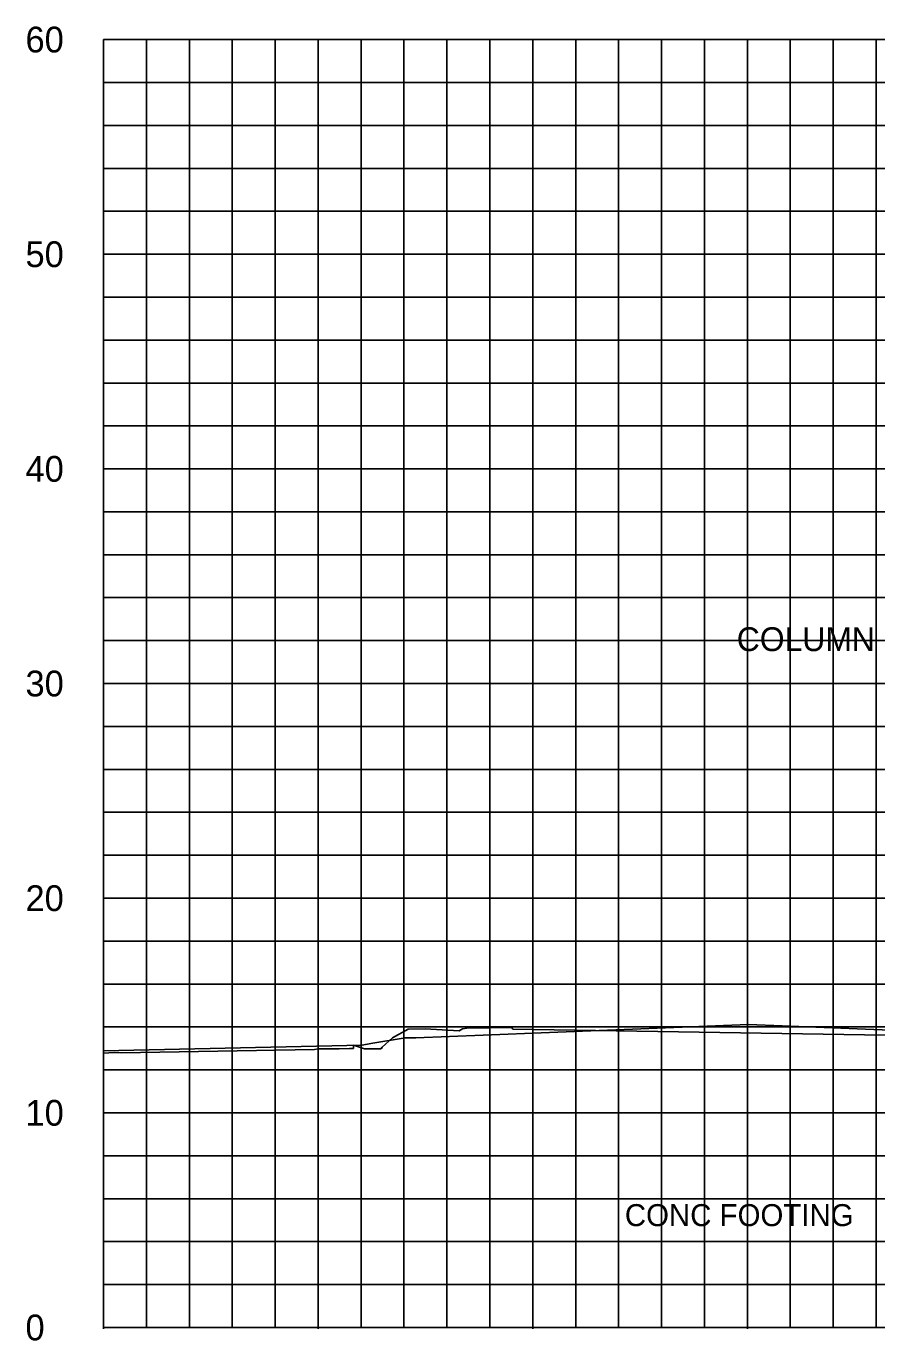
# Model space of a CAD drawing. Extents: x 2193008 to 2198143, y 1236112 to 1237864.
# Drawn here: x 2194694.1 to 2194733.7, y 1237162.5 to 1237223.7 of the extents above; entities that cross this region are included whole.
import ezdxf

# ---------------------------------------------------------------- set-up
doc = ezdxf.new("R2010")
doc.units = 0
for name, color, linetype in [('31', 7, 'Continuous'), ('60', 7, 'Continuous'), ('CL-CNST', 7, 'Continuous'), ('Level 55', 7, 'Continuous'), ('Level 62', 7, 'Continuous'), ('M-ROADS', 7, 'Continuous')]:
    doc.layers.add(name, color=color, linetype=linetype)

msp = doc.modelspace()

# ---------------------------------------------------------------- linework, layer by layer
at = {"layer": '60'}
for p, q in [((2194697.688, 1237163.106), (2194697.688, 1237223.106)), ((2194697.688, 1237163.046), (2194697.688, 1237163.106)), ((2194697.688, 1237163.106), (2194827.688, 1237163.106)), ((2194707.688, 1237163.046), (2194707.688, 1237163.106)), ((2194717.688, 1237163.046), (2194717.688, 1237163.106)), ((2194727.688, 1237163.046), (2194727.688, 1237163.106))]:
    msp.add_line(p, q, dxfattribs=at)
at = {"layer": 'CL-CNST'}
msp.add_lwpolyline([(2194697.688, 1237175.995), (2194709.741, 1237176.26), (2194710.142, 1237176.328), (2194711.741, 1237176.6), (2194711.841, 1237176.6), (2194712.241, 1237176.6), (2194715.381, 1237176.726), (2194727.74, 1237177.22), (2194730.881, 1237177.095), (2194743.239, 1237176.6), (2194743.639, 1237176.6), (2194743.739, 1237176.6), (2194744.14, 1237176.532), (2194745.739, 1237176.26), (2194755.304, 1237176.05), (2194793.33, 1237175.213)], dxfattribs=at)
at = {"layer": 'Level 62'}
for p, q in [((2194697.688, 1237223.106), (2194827.688, 1237223.106)), ((2194699.688, 1237163.106), (2194699.688, 1237223.106)), ((2194701.688, 1237163.106), (2194701.688, 1237223.106)), ((2194703.688, 1237163.106), (2194703.688, 1237223.106)), ((2194705.688, 1237163.106), (2194705.688, 1237223.106)), ((2194707.688, 1237163.106), (2194707.688, 1237223.106)), ((2194709.688, 1237163.106), (2194709.688, 1237223.106)), ((2194711.688, 1237163.106), (2194711.688, 1237223.106)), ((2194713.688, 1237163.106), (2194713.688, 1237223.106)), ((2194715.688, 1237163.106), (2194715.688, 1237223.106)), ((2194717.688, 1237163.106), (2194717.688, 1237223.106)), ((2194719.688, 1237163.106), (2194719.688, 1237223.106)), ((2194721.688, 1237163.106), (2194721.688, 1237223.106)), ((2194723.688, 1237163.106), (2194723.688, 1237223.106)), ((2194725.688, 1237163.106), (2194725.688, 1237223.106)), ((2194727.688, 1237163.106), (2194727.688, 1237223.106)), ((2194729.688, 1237163.106), (2194729.688, 1237223.106)), ((2194731.688, 1237163.106), (2194731.688, 1237223.106)), ((2194733.688, 1237163.106), (2194733.688, 1237223.106)), ((2194697.688, 1237221.106), (2194827.688, 1237221.106)), ((2194697.688, 1237219.106), (2194827.688, 1237219.106)), ((2194697.688, 1237217.106), (2194827.688, 1237217.106)), ((2194697.688, 1237215.106), (2194827.688, 1237215.106)), ((2194697.688, 1237213.106), (2194827.688, 1237213.106)), ((2194697.688, 1237211.106), (2194827.688, 1237211.106)), ((2194697.688, 1237209.106), (2194827.688, 1237209.106)), ((2194697.688, 1237207.106), (2194827.688, 1237207.106)), ((2194697.688, 1237205.106), (2194827.688, 1237205.106)), ((2194697.688, 1237203.106), (2194827.688, 1237203.106)), ((2194697.688, 1237201.106), (2194827.688, 1237201.106)), ((2194697.688, 1237199.106), (2194827.688, 1237199.106)), ((2194697.688, 1237197.106), (2194827.688, 1237197.106)), ((2194697.688, 1237195.106), (2194827.688, 1237195.106)), ((2194697.688, 1237193.106), (2194827.688, 1237193.106)), ((2194697.688, 1237191.106), (2194827.688, 1237191.106)), ((2194697.688, 1237189.106), (2194827.688, 1237189.106)), ((2194697.688, 1237187.106), (2194827.688, 1237187.106)), ((2194697.688, 1237185.106), (2194827.688, 1237185.106)), ((2194697.688, 1237183.106), (2194827.688, 1237183.106)), ((2194697.688, 1237181.106), (2194827.688, 1237181.106)), ((2194697.688, 1237179.106), (2194827.688, 1237179.106)), ((2194697.688, 1237177.106), (2194827.688, 1237177.106)), ((2194697.688, 1237175.106), (2194827.688, 1237175.106)), ((2194697.688, 1237173.106), (2194827.688, 1237173.106)), ((2194697.688, 1237171.106), (2194827.688, 1237171.106)), ((2194697.688, 1237169.106), (2194827.688, 1237169.106)), ((2194697.688, 1237167.106), (2194827.688, 1237167.106)), ((2194697.688, 1237165.106), (2194827.688, 1237165.106)), ((2194697.688, 1237163.106), (2194827.688, 1237163.106))]:
    msp.add_line(p, q, dxfattribs=at)
at = {"layer": 'M-ROADS'}
msp.add_lwpolyline([(2194697.688, 1237175.885), (2194698.182, 1237175.918), (2194698.512, 1237175.901), (2194707.523, 1237176.06), (2194707.688, 1237176.081), (2194708.662, 1237176.088), (2194709.15, 1237176.106), (2194709.335, 1237176.104), (2194709.337, 1237176.252), (2194709.852, 1237176.087), (2194710.58, 1237176.082), (2194710.582, 1237176.097), (2194710.625, 1237176.091), (2194710.664, 1237176.169), (2194711.147, 1237176.593), (2194711.878, 1237177.009), (2194712.674, 1237177.026), (2194714.256, 1237176.921), (2194714.411, 1237177.026), (2194714.611, 1237177.049), (2194716.708, 1237177.074), (2194716.763, 1237177.01), (2194740.861, 1237176.616)], dxfattribs=at)

# ---------------------------------------------------------------- texts
at = {"layer": '31'}
for s, p in [('60', (2194694.054, 1237222.506)), ('50', (2194694.054, 1237212.506)), ('40', (2194694.054, 1237202.506)), ('30', (2194694.054, 1237192.506)), ('20', (2194694.054, 1237182.506)), ('10', (2194694.054, 1237172.506)), ('0', (2194694.054, 1237162.506))]:
    msp.add_text(s, height=1.2, dxfattribs=at).set_placement(p)
at = {"layer": 'Level 55'}
for s, height, p in [('COLUMN', 1.1105, (2194727.192, 1237194.616)), ('CONC FOOTING', 1.02464, (2194721.979, 1237167.827))]:
    msp.add_text(s, height=height, dxfattribs=at).set_placement(p)

doc.saveas('drawing.dxf')
